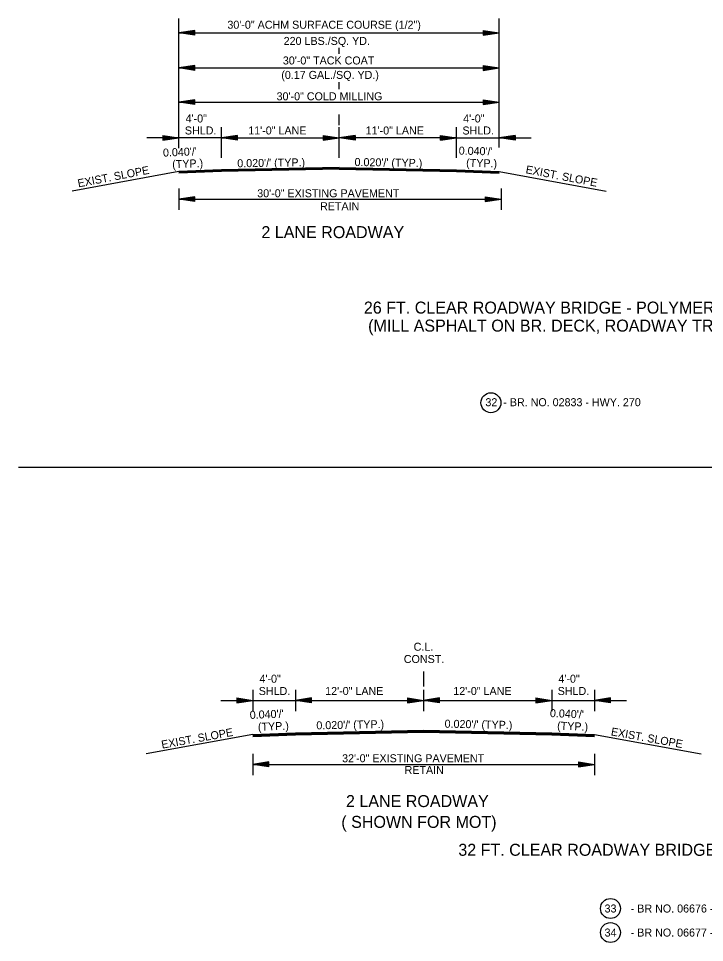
# Model space of a CAD drawing. Extents: x 550980 to 1930787, y -1972975 to 596640.
# Drawn here: x 550993 to 551635, y -1960354 to -1959488 of the extents above; entities that cross this region are included whole.
import ezdxf

# ---------------------------------------------------------------- set-up
doc = ezdxf.new("R2010")
doc.units = 0
doc.layers.add('R_Border', color=7, linetype='Continuous')
doc.layers.add('R_Draft', color=7, linetype='Continuous')

# ---------------------------------------------------------------- blocks, each defined once
blk = doc.blocks.new('BPPOLY')
at = {"layer": 'R_Border'}
blk.add_circle((0, 0), 9.34, dxfattribs=at)
blk = doc.blocks.new('ARROW')
at = {"layer": 'R_Draft'}
for p, q in [((-2, 0.3), (0, 0)), ((-2, 0.3), (-2, -0.3)), ((-2, 0.25), (-0.334, 0)), ((-2, 0.199), (-0.678, 0)), ((-2, 0.149), (-1.011, 0)), ((-2, 0.097), (-1.35, 0)), ((-2, 0.047), (-1.684, 0)), ((-2, -0.3), (0, 0)), ((-2, -0.098), (-1.35, 0)), ((-2, -0.199), (-0.678, 0)), ((-2, -0.25), (-0.334, 0)), ((-2, -0.149), (-1.011, 0)), ((-2, -0.047), (-1.684, 0))]:
    blk.add_line(p, q, dxfattribs=at)

msp = doc.modelspace()

# ---------------------------------------------------------------- linework, layer by layer
at = {"layer": 'R_Border'}
for p, q in [((551183.16, -1959629.58), (551143.16, -1959631.18)), ((551183.16, -1959629.88), (551143.16, -1959631.48)), ((551183.16, -1959630.18), (551143.16, -1959631.78)), ((551183.16, -1959630.48), (551143.16, -1959632.08)), ((551183.16, -1959630.78), (551143.16, -1959632.38)), ((551183.16, -1959631.08), (551143.16, -1959632.68)), ((551183.16, -1959631.25), (551143.16, -1959632.85)), ((551403.16, -1959629.58), (551443.16, -1959631.18)), ((551403.16, -1959629.88), (551443.16, -1959631.48)), ((551403.16, -1959630.18), (551443.16, -1959631.78)), ((551403.16, -1959630.48), (551443.16, -1959632.08)), ((551403.16, -1959630.78), (551443.16, -1959632.38)), ((551403.16, -1959631.08), (551443.16, -1959632.68)), ((551403.16, -1959631.25), (551443.16, -1959632.85)), ((550992.91, -1959908.21), (552054.18, -1959908.21)), ((551372.36, -1960099.68), (551372.36, -1960113.68)), ((551212.36, -1960116.68), (551212.36, -1960136.68)), ((551252.36, -1960116.68), (551252.36, -1960136.68)), ((551372.36, -1960116.68), (551372.36, -1960136.68)), ((551492.36, -1960116.68), (551492.36, -1960136.68)), ((551532.36, -1960116.68), (551532.36, -1960136.68)), ((551182.36, -1960126.68), (551562.36, -1960126.68)), ((551372.22, -1960127.29), (551372.22, -1960127.29)), ((551212.36, -1960158.68), (551112.36, -1960176.68)), ((551532.36, -1960158.68), (551632.36, -1960176.68)), ((551212.36, -1960176.68), (551212.36, -1960196.68)), ((551532.36, -1960176.68), (551532.36, -1960196.68)), ((551212.36, -1960186.68), (551532.36, -1960186.68))]:
    msp.add_line(p, q, dxfattribs=at)
for points in [[(551212.36, -1960158.68), (551252.36, -1960157.08), (551372.36, -1960154.68), (551492.36, -1960157.08), (551532.36, -1960158.68)], [(551212.36, -1960158.98), (551252.36, -1960157.38), (551372.36, -1960154.98), (551492.36, -1960157.38), (551532.36, -1960158.98)], [(551212.36, -1960159.28), (551252.36, -1960157.68), (551372.36, -1960155.28), (551492.36, -1960157.68), (551532.36, -1960159.28)], [(551212.36, -1960159.58), (551252.36, -1960157.98), (551372.36, -1960155.58), (551492.36, -1960157.98), (551532.36, -1960159.58)], [(551212.36, -1960159.88), (551252.36, -1960158.28), (551372.36, -1960155.88), (551492.36, -1960158.28), (551532.36, -1960159.88)], [(551212.36, -1960160.18), (551252.36, -1960158.58), (551372.36, -1960156.18), (551492.36, -1960158.58), (551532.36, -1960160.18)], [(551212.36, -1960160.48), (551252.36, -1960158.88), (551372.36, -1960156.48), (551492.36, -1960158.88), (551532.36, -1960160.48)]]:
    msp.add_lwpolyline(points, dxfattribs=at)
msp.add_circle((551435.42, -1959847.9), 9.34, dxfattribs=at)
at = {"layer": 'R_Draft'}
for p, q in [((551143.16, -1959609.27), (551143.16, -1959487.93)), ((551443.16, -1959608.8), (551443.16, -1959487.93)), ((551158.16, -1959499.05), (551143.16, -1959501.3)), ((551143.16, -1959501.3), (551443.16, -1959501.3)), ((551158.16, -1959503.55), (551143.16, -1959501.3)), ((551158.16, -1959499.42), (551145.66, -1959501.3)), ((551158.16, -1959503.17), (551145.66, -1959501.3)), ((551158.16, -1959499.8), (551148.24, -1959501.3)), ((551158.16, -1959502.79), (551148.24, -1959501.3)), ((551158.16, -1959500.18), (551150.74, -1959501.3)), ((551158.16, -1959502.41), (551150.74, -1959501.3)), ((551158.16, -1959500.56), (551153.28, -1959501.3)), ((551158.16, -1959502.02), (551153.28, -1959501.3)), ((551158.16, -1959500.94), (551155.79, -1959501.3)), ((551158.16, -1959501.65), (551155.79, -1959501.3)), ((551158.16, -1959503.55), (551158.16, -1959499.05)), ((551428.16, -1959499.05), (551443.16, -1959501.3)), ((551428.16, -1959499.05), (551428.16, -1959503.55)), ((551428.16, -1959499.42), (551440.65, -1959501.3)), ((551428.16, -1959499.8), (551438.07, -1959501.3)), ((551428.16, -1959500.18), (551435.57, -1959501.3)), ((551428.16, -1959500.57), (551433.03, -1959501.3)), ((551428.16, -1959500.94), (551430.53, -1959501.3)), ((551428.16, -1959503.55), (551443.16, -1959501.3)), ((551428.16, -1959502.03), (551433.03, -1959501.3)), ((551428.16, -1959502.79), (551438.07, -1959501.3)), ((551428.16, -1959503.17), (551440.65, -1959501.3)), ((551428.16, -1959502.41), (551435.57, -1959501.3)), ((551428.16, -1959501.65), (551430.53, -1959501.3)), ((551293.16, -1959521.04), (551293.16, -1959515.5)), ((551158.16, -1959532.01), (551143.16, -1959534.26)), ((551158.16, -1959536.51), (551158.16, -1959532.01)), ((551428.16, -1959532.01), (551443.16, -1959534.26)), ((551428.16, -1959532.01), (551428.16, -1959536.51)), ((551143.16, -1959534.26), (551443.16, -1959534.26)), ((551158.16, -1959536.51), (551143.16, -1959534.26)), ((551158.16, -1959532.39), (551145.66, -1959534.26)), ((551158.16, -1959536.14), (551145.66, -1959534.26)), ((551158.16, -1959532.77), (551148.24, -1959534.26)), ((551158.16, -1959535.76), (551148.24, -1959534.26)), ((551158.16, -1959533.15), (551150.74, -1959534.26)), ((551158.16, -1959535.38), (551150.74, -1959534.26)), ((551158.16, -1959533.53), (551153.28, -1959534.26)), ((551158.16, -1959534.99), (551153.28, -1959534.26)), ((551158.16, -1959533.91), (551155.79, -1959534.26)), ((551158.16, -1959534.62), (551155.79, -1959534.26)), ((551428.16, -1959532.39), (551440.65, -1959534.26)), ((551428.16, -1959532.77), (551438.07, -1959534.26)), ((551428.16, -1959533.15), (551435.57, -1959534.26)), ((551428.16, -1959533.54), (551433.03, -1959534.26)), ((551428.16, -1959533.91), (551430.53, -1959534.26)), ((551428.16, -1959536.51), (551443.16, -1959534.26)), ((551428.16, -1959535), (551433.03, -1959534.26)), ((551428.16, -1959535.76), (551438.07, -1959534.26)), ((551428.16, -1959536.14), (551440.65, -1959534.26)), ((551428.16, -1959535.38), (551435.57, -1959534.26)), ((551428.16, -1959534.62), (551430.53, -1959534.26)), ((551293.16, -1959554.01), (551293.16, -1959547.59)), ((551158.16, -1959563.99), (551143.16, -1959566.24)), ((551143.16, -1959566.24), (551443.16, -1959566.24)), ((551158.16, -1959568.49), (551143.16, -1959566.24)), ((551158.16, -1959564.36), (551145.66, -1959566.24)), ((551158.16, -1959568.11), (551145.66, -1959566.24)), ((551158.16, -1959564.75), (551148.24, -1959566.24)), ((551158.16, -1959567.73), (551148.24, -1959566.24)), ((551158.16, -1959565.12), (551150.74, -1959566.24)), ((551158.16, -1959567.36), (551150.74, -1959566.24)), ((551158.16, -1959565.5), (551153.28, -1959566.24)), ((551158.16, -1959566.97), (551153.28, -1959566.24)), ((551158.16, -1959565.89), (551155.79, -1959566.24)), ((551158.16, -1959566.59), (551155.79, -1959566.24)), ((551158.16, -1959568.49), (551158.16, -1959563.99)), ((551428.16, -1959563.99), (551443.16, -1959566.24)), ((551428.16, -1959563.99), (551428.16, -1959568.49)), ((551428.16, -1959564.36), (551440.65, -1959566.24)), ((551428.16, -1959564.75), (551438.07, -1959566.24)), ((551428.16, -1959565.12), (551435.57, -1959566.24)), ((551428.16, -1959565.51), (551433.03, -1959566.24)), ((551428.16, -1959565.89), (551430.53, -1959566.24)), ((551428.16, -1959568.49), (551443.16, -1959566.24)), ((551428.16, -1959566.97), (551433.03, -1959566.24)), ((551428.16, -1959567.73), (551438.07, -1959566.24)), ((551428.16, -1959568.11), (551440.65, -1959566.24)), ((551428.16, -1959567.36), (551435.57, -1959566.24)), ((551428.16, -1959566.59), (551430.53, -1959566.24)), ((551293.16, -1959587.76), (551293.16, -1959577.89)), ((551183.16, -1959618.43), (551183.16, -1959589.88)), ((551293.16, -1959618.43), (551293.16, -1959589.88)), ((551403.16, -1959618.43), (551403.16, -1959589.88)), ((551183.16, -1959599.77), (551113.16, -1959599.77)), ((551128.16, -1959597.52), (551143.16, -1959599.77)), ((551128.16, -1959597.52), (551128.16, -1959602.02)), ((551128.16, -1959597.9), (551140.65, -1959599.77)), ((551128.16, -1959598.28), (551138.07, -1959599.77)), ((551128.16, -1959598.66), (551135.57, -1959599.77)), ((551128.16, -1959599.05), (551133.03, -1959599.77)), ((551128.16, -1959599.42), (551130.53, -1959599.77)), ((551128.16, -1959602.02), (551143.16, -1959599.77)), ((551128.16, -1959600.51), (551133.03, -1959599.77)), ((551128.16, -1959601.27), (551138.07, -1959599.77)), ((551128.16, -1959601.65), (551140.65, -1959599.77)), ((551128.16, -1959600.89), (551135.57, -1959599.77)), ((551128.16, -1959600.13), (551130.53, -1959599.77)), ((551198.16, -1959597.52), (551183.16, -1959599.77)), ((551198.16, -1959602.02), (551183.16, -1959599.77)), ((551183.16, -1959599.77), (551293.16, -1959599.77)), ((551198.16, -1959597.9), (551185.66, -1959599.77)), ((551198.16, -1959601.65), (551185.66, -1959599.77)), ((551198.16, -1959598.28), (551188.24, -1959599.77)), ((551198.16, -1959601.27), (551188.24, -1959599.77)), ((551198.16, -1959598.66), (551190.74, -1959599.77)), ((551198.16, -1959600.89), (551190.74, -1959599.77)), ((551198.16, -1959599.04), (551193.28, -1959599.77)), ((551198.16, -1959600.5), (551193.28, -1959599.77)), ((551198.16, -1959599.42), (551195.79, -1959599.77)), ((551198.16, -1959600.13), (551195.79, -1959599.77)), ((551198.16, -1959602.02), (551198.16, -1959597.52)), ((551278.16, -1959597.52), (551293.16, -1959599.77)), ((551278.16, -1959597.52), (551278.16, -1959602.02)), ((551278.16, -1959597.9), (551290.65, -1959599.77)), ((551278.16, -1959598.28), (551288.07, -1959599.77)), ((551278.16, -1959598.66), (551285.57, -1959599.77)), ((551278.16, -1959599.05), (551283.03, -1959599.77)), ((551278.16, -1959599.42), (551280.53, -1959599.77)), ((551278.16, -1959602.02), (551293.16, -1959599.77)), ((551278.16, -1959600.51), (551283.03, -1959599.77)), ((551278.16, -1959601.27), (551288.07, -1959599.77)), ((551278.16, -1959601.65), (551290.65, -1959599.77)), ((551278.16, -1959600.89), (551285.57, -1959599.77)), ((551278.16, -1959600.13), (551280.53, -1959599.77)), ((551308.16, -1959597.52), (551293.16, -1959599.77)), ((551403.16, -1959599.77), (551293.16, -1959599.77)), ((551308.16, -1959602.02), (551293.16, -1959599.77)), ((551308.16, -1959597.9), (551295.66, -1959599.77)), ((551308.16, -1959601.65), (551295.66, -1959599.77)), ((551308.16, -1959598.28), (551298.24, -1959599.77)), ((551308.16, -1959601.27), (551298.24, -1959599.77)), ((551308.16, -1959598.66), (551300.74, -1959599.77)), ((551308.16, -1959600.89), (551300.74, -1959599.77)), ((551308.16, -1959599.05), (551303.28, -1959599.77)), ((551308.16, -1959600.51), (551303.28, -1959599.77)), ((551308.16, -1959599.42), (551305.79, -1959599.77)), ((551308.16, -1959600.13), (551305.79, -1959599.77)), ((551308.16, -1959597.52), (551308.16, -1959602.02)), ((551388.16, -1959597.52), (551403.16, -1959599.77)), ((551388.16, -1959602.02), (551388.16, -1959597.52)), ((551388.16, -1959597.9), (551400.65, -1959599.77)), ((551388.16, -1959598.28), (551398.07, -1959599.77)), ((551388.16, -1959598.66), (551395.57, -1959599.77)), ((551388.16, -1959599.04), (551393.03, -1959599.77)), ((551388.16, -1959599.42), (551390.53, -1959599.77)), ((551388.16, -1959602.02), (551403.16, -1959599.77)), ((551388.16, -1959600.5), (551393.03, -1959599.77)), ((551388.16, -1959601.27), (551398.07, -1959599.77)), ((551388.16, -1959601.65), (551400.65, -1959599.77)), ((551388.16, -1959600.89), (551395.57, -1959599.77)), ((551388.16, -1959600.13), (551390.53, -1959599.77)), ((551403.16, -1959599.77), (551473.16, -1959599.77)), ((551458.16, -1959597.52), (551443.16, -1959599.77)), ((551458.16, -1959602.02), (551443.16, -1959599.77)), ((551458.16, -1959597.9), (551445.66, -1959599.77)), ((551458.16, -1959601.65), (551445.66, -1959599.77)), ((551458.16, -1959598.28), (551448.24, -1959599.77)), ((551458.16, -1959601.27), (551448.24, -1959599.77)), ((551458.16, -1959598.66), (551450.74, -1959599.77)), ((551458.16, -1959600.89), (551450.74, -1959599.77)), ((551458.16, -1959599.05), (551453.28, -1959599.77)), ((551458.16, -1959600.51), (551453.28, -1959599.77)), ((551458.16, -1959599.42), (551455.79, -1959599.77)), ((551458.16, -1959600.13), (551455.79, -1959599.77)), ((551458.16, -1959597.52), (551458.16, -1959602.02)), ((551143.16, -1959631.18), (551043.09, -1959649.56)), ((551293.16, -1959627.38), (551183.16, -1959629.58)), ((551293.19, -1959627.68), (551183.16, -1959629.88)), ((551293.18, -1959627.98), (551183.16, -1959630.18)), ((551293.17, -1959628.28), (551183.16, -1959630.48)), ((551293.18, -1959628.58), (551183.16, -1959630.78)), ((551293.19, -1959628.88), (551183.16, -1959631.08)), ((551293.19, -1959629.05), (551183.16, -1959631.25)), ((551293.12, -1959629.05), (551403.16, -1959631.25)), ((551293.13, -1959628.58), (551403.16, -1959630.78)), ((551293.13, -1959628.88), (551403.16, -1959631.08)), ((551293.14, -1959627.98), (551403.16, -1959630.18)), ((551293.14, -1959628.28), (551403.16, -1959630.48)), ((551293.15, -1959627.68), (551403.16, -1959629.88)), ((551293.16, -1959627.38), (551403.16, -1959629.58)), ((551443.16, -1959631.18), (551543.22, -1959649.56)), ((551143.16, -1959647.24), (551143.16, -1959667.24)), ((551445.16, -1959647.24), (551445.16, -1959667.24)), ((551158.16, -1959654.99), (551143.16, -1959657.24)), ((551143.16, -1959657.24), (551443.16, -1959657.24)), ((551158.16, -1959659.49), (551143.16, -1959657.24)), ((551158.16, -1959655.36), (551145.66, -1959657.24)), ((551158.16, -1959659.11), (551145.66, -1959657.24)), ((551158.16, -1959655.75), (551148.24, -1959657.24)), ((551158.16, -1959658.73), (551148.24, -1959657.24)), ((551158.16, -1959656.12), (551150.74, -1959657.24)), ((551158.16, -1959658.36), (551150.74, -1959657.24)), ((551158.16, -1959656.5), (551153.28, -1959657.24)), ((551158.16, -1959657.97), (551153.28, -1959657.24)), ((551158.16, -1959656.89), (551155.79, -1959657.24)), ((551158.16, -1959657.59), (551155.79, -1959657.24)), ((551158.16, -1959659.49), (551158.16, -1959654.99)), ((551430.16, -1959654.99), (551445.16, -1959657.24)), ((551430.16, -1959654.99), (551430.16, -1959659.49)), ((551430.16, -1959655.36), (551442.65, -1959657.24)), ((551430.16, -1959655.75), (551440.07, -1959657.24)), ((551430.16, -1959656.12), (551437.57, -1959657.24)), ((551430.16, -1959656.51), (551435.03, -1959657.24)), ((551430.16, -1959656.89), (551432.53, -1959657.24)), ((551430.16, -1959659.49), (551445.16, -1959657.24)), ((551430.16, -1959657.97), (551435.03, -1959657.24)), ((551430.16, -1959658.73), (551440.07, -1959657.24)), ((551430.16, -1959659.11), (551442.65, -1959657.24)), ((551430.16, -1959658.36), (551437.57, -1959657.24)), ((551430.16, -1959657.59), (551432.53, -1959657.24))]:
    msp.add_line(p, q, dxfattribs=at)

# ---------------------------------------------------------------- block references
at = {"layer": 'R_Border', "xscale": 7.5, "yscale": 7.5}
for p in [(551212.36, -1960126.68), (551372.36, -1960126.68), (551492.36, -1960126.68), (551532.36, -1960186.68)]:
    msp.add_blockref('ARROW', p, dxfattribs=at)
at = {"layer": 'R_Border', "xscale": 7.5, "yscale": 7.5, "rotation": 180}
for p in [(551252.36, -1960126.68), (551372.36, -1960126.68), (551532.36, -1960126.68), (551212.36, -1960186.68)]:
    msp.add_blockref('ARROW', p, dxfattribs=at)
at = {"layer": 'R_Border'}
for p in [(551547.36, -1960321.68), (551547.36, -1960344.2)]:
    msp.add_blockref('BPPOLY', p, dxfattribs=at)

# ---------------------------------------------------------------- texts
for s, height, p in [('C.L.', 7.5, (551363.03, -1960080.2)), ('CONST.', 7.5, (551353.82, -1960091.7)), ('4\'-0"', 7.5, (551218.63, -1960110.18)), ('4\'-0"', 7.5, (551498.63, -1960110.18)), ('SHLD.', 7.5, (551217.95, -1960121.68)), ('12\'-0" LANE', 7.5, (551280.18, -1960121.68)), ('12\'-0" LANE', 7.5, (551400.18, -1960121.68)), ('SHLD.', 7.5, (551497.95, -1960121.68)), ('32\'-0" EXISTING PAVEMENT', 7.5, (551296.03, -1960184.68)), ('RETAIN', 7.5, (551354.56, -1960195.68)), ('2 LANE ROADWAY', 11.25, (551299.64, -1960226.68)), ('( SHOWN FOR MOT)', 11.25, (551295.3, -1960246.16)), ('32 FT. CLEAR ROADWAY BRIDGE - POLYMER OVERLAY', 11.25, (551404.88, -1960272.3)), ('33', 7.5, (551541.87, -1960325.43)), ('- BR NO. 06676 - HWY. 10', 7.5, (551566.36, -1960325.43)), ('34', 7.5, (551541.87, -1960347.95)), ('- BR NO. 06677 - HWY. 10', 7.5, (551566.36, -1960347.95))]:
    msp.add_text(s, height=height, dxfattribs=at).set_placement(p)
for s, rotation, p in [("0.040'/'", 2.2916, (551209.66, -1960144.08)), ("0.040'/'", 357.7084, (551490.58, -1960142.29)), ('(TYP.)', 2.2916, (551217.32, -1960155.28)), ("0.020'/' (TYP.)", 1.1458, (551271.98, -1960153.88)), ("0.020'/' (TYP.)", 358.8542, (551391.98, -1960152.27)), ('(TYP.)', 357.7084, (551497.32, -1960154.07)), ('EXIST. SLOPE', 10.204, (551127.43, -1960171.96)), ('EXIST. SLOPE', 349.796, (551547.43, -1960159.39))]:
    msp.add_text(s, height=7.5, rotation=rotation, dxfattribs=at).set_placement(p)
at = {"layer": 'R_Draft'}
for s, height, p in [('30\'-0" ACHM SURFACE COURSE (1/2")', 7.5, (551188.57, -1959497.53)), ('220 LBS./SQ. YD. ', 7.5, (551241.28, -1959512.71)), ('30\'-0" TACK COAT', 7.5, (551240.51, -1959531)), ('(0.17 GAL./SQ. YD.)', 7.5, (551239.07, -1959544.54)), ('30\'-0" COLD MILLING ', 7.5, (551234.66, -1959564.57)), ('4\'-0"', 7.5, (551149.43, -1959585.35)), ('4\'-0"', 7.5, (551409.43, -1959585.35)), ('SHLD.', 7.5, (551148.75, -1959596.6)), ('11\'-0" LANE', 7.5, (551208.1, -1959596.6)), ('11\'-0" LANE', 7.5, (551318.1, -1959596.6)), ('SHLD.', 7.5, (551408.75, -1959596.6)), ('30\'-0" EXISTING PAVEMENT', 7.5, (551216.53, -1959655.41)), ('RETAIN', 7.5, (551275.35, -1959667.5)), ('2 LANE ROADWAY', 11.25, (551220.43, -1959693.71)), ('26 FT. CLEAR ROADWAY BRIDGE - POLYMER OVERLAY', 11.25, (551316.41, -1959764.39)), ('(MILL ASPHALT ON BR. DECK, ROADWAY TRANSITIONS)', 11.25, (551320.4, -1959781.27)), ('32  - BR. NO. 02833 - HWY. 270', 7.5, (551430.26, -1959851.14))]:
    msp.add_text(s, height=height, dxfattribs=at).set_placement(p)
for s, rotation, p in [("  0.040'/'", 2.44797, (551122.83, -1959617.65)), ("0.040'/'", 358.68162, (551405.19, -1959615.43)), ("0.020'/' (TYP.)", 0.87191, (551197.9, -1959627.34)), ("0.020'/' (TYP.)", 359.12809, (551307.64, -1959626.11)), ('EXIST. SLOPE', 10.88286, (551049.07, -1959646.18)), (' (TYP.)', 2.44797, (551134.25, -1959628.42)), ('(TYP.)', 358.68162, (551412.14, -1959626.84)), ('EXIST. SLOPE', 349.11714, (551467.54, -1959632.78))]:
    msp.add_text(s, height=7.5, rotation=rotation, dxfattribs=at).set_placement(p)

doc.saveas('drawing.dxf')
